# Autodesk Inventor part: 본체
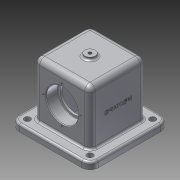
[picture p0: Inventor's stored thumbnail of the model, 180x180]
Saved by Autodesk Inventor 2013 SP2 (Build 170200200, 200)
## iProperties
Created: 2022-07
Part Number: 본체
Material: 알루미늄 6061
Document SubType Name: Modeling
Designer: i
Density: 2.71 g/cm^3
Mass: 1063.76 g
Surface Area: 721.846 cm^2
Volume: 392.531 cm^3
Author: i
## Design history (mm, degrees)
sketch "스케치1"
  geometry: L1 (-41, -40)-(41, -40); L2 (41, -40)-(41, 40); L3 (41, 40)-(-41, 40); L4 (-41, 40)-(-41, -40); L5 (-41, -40)-(41, 40); L6 (41, -40)-(-41, 40); 1 further point
  constraints: 12 end point, 2 midpoint, 2 parallel, 1 horizontal, 1 perpendicular
  dimensions: "d0" = 82 distance of L2.end L3.end; "d2" = 80 distance of L1.end L2.end
extrude "돌출1" new body sketch "스케치1" stored distance "d3" = 82; taper "d4" = 0 deg
sketch "스케치2"
  geometry: L1 (-17, -99)-(99, -99); L2 (99, -99)-(99, 17); L3 (99, 17)-(-17, 17); L4 (-17, 17)-(-17, -99); L5 (-17, -99)-(99, 17); L6 (99, -99)-(-17, 17); 1 further point
  constraints: 12 end point, 2 midpoint, 2 parallel, 1 horizontal, 1 perpendicular
  dimensions: "d5" = 116 distance of L3.end L2.end; "d6" = 116 distance of L2.end L1.end
extrude "돌출2" join sketch "스케치2" distance "d7" = 10; taper "d8" = 0 deg
sketch "스케치3"
  geometry: L1 (41, 40)-(-41, 40) reference; C1 r 23.5 at (0, -2); 1 further point
  constraints: 1 centre point, 1 vertical alignment
  dimensions: "d9" = 47 diameter of C1; "d10" = 42 distance from line of L1 C1.centre
extrude "돌출3" cut sketch "스케치3" distance "d11" = 17; taper "d12" = 0 deg
sketch "스케치4"
  geometry: L1 (11, -62)-(71, -62); L2 (71, -62)-(71, -20); L3 (71, -20)-(11, -20); L4 (11, -20)-(11, -62); L5 (11, -62)-(71, -20); L6 (71, -62)-(11, -20); 1 further point
  constraints: 12 end point, 2 midpoint, 2 parallel, 1 horizontal, 1 perpendicular
  dimensions: "d13" = 60 distance of L3.end L2.end; "d14" = 42 distance of L2.end L1.end
extrude "돌출4" cut sketch "스케치4" distance "d15" = 80; taper "d16" = 0 deg
sketch "스케치5"
  geometry: C1 r 23.5 at (0, 0) reference; C2 r 20 at (0, 0); 1 further point
  constraints: 1 centre point, 1 coincident
  dimensions: "d17" = 40 diameter of C2
extrude "돌출5" cut sketch "스케치5" stored distance "d18" = 80; taper "d19" = 0 deg
fillet "모깎기1" dims "d20" = 0.6
fillet "모깎기2" dims "d21" = 3
fillet "모깎기3" dims "d22" = 3
chamfer "모따기1" distance "d23" = 1; stored, may be unused: second distance "d24" = 2, angle "d25" = 45 deg
fillet "모깎기4" dims "d26" = 8
fillet "모깎기5" dims "d27" = 8
fillet "모깎기6" dims "d28" = 12
fillet "모깎기7" dims "d29" = 3
sketch "스케치6"
  geometry: C1 r 4.5 at (-5, 87); C2 r 4.5 at (87, 87); C3 r 4.5 at (87, -5); C4 r 4.5 at (-5, -5); A1 r 12 centre (-5, 87) between (-5, 99) and (-17, 87) reference; A2 r 12 centre (-5, -5) between (-17, -5) and (-5, -17) reference; A3 r 12 centre (87, -5) between (87, -17) and (99, -5) reference; A4 r 12 centre (87, 87) between (99, 87) and (87, 99) reference; 1 further point
  constraints: 4 centre point, 4 coincident
  dimensions: "d30" = 9 diameter of C1; "d31" = 9 diameter of C2; "d33" = 9 diameter of C3; "d34" = 9 diameter of C4
extrude "돌출6" cut sketch "스케치6" stored distance "d35" = 80; taper "d36" = 0 deg
fillet "모깎기8" dims "d37" = 3
sketch "스케치7"
  geometry: C1 r 7.5 at (33, 33); 1 further point
  constraints: 1 centre point, 1 coincident
  dimensions: "d38" = 15 diameter of C1
extrude "돌출7" join sketch "스케치7" distance "d39" = 4; taper "d40" = 0 deg
sketch "스케치8"
  geometry: C1 r 7.5 at (0, 0) reference; 1 further point
  constraints: 1 coincident
hole "구멍1" sketch "스케치8" at (0, 0) diameter "d41" = 4.917; stored, may be unused: countersink angle "d45" = 90 deg, drill point angle "d47" = 118 deg; dims "d42" = 6, "d43" = 4, "d44" = 2, "d46" = 8
sketch "스케치9"
  geometry: C1 r 24.5 at (0, -2) reference; 2 further points
  constraints: 1 vertical alignment
  dimensions: "d48" = 27 distance of C1.centre point (0, 25)
hole "구멍2" sketch "스케치9" at (0, 25) diameter "d49" = 3.242; stored, may be unused: countersink angle "d53" = 90 deg, drill point angle "d55" = 118 deg; dims "d50" = 8, "d51" = 4, "d52" = 2, "d54" = 10
fillet "모깎기9" dims "d59" = 3
sketch "스케치10"
  geometry: L1 (79, -82)-(-13, -82) reference; 2 further points
  constraints: 1 vertical alignment, 1 other
  dimensions: "d60" = 48 distance from line of L1 point (33, -34)
feature "엠보싱1" sketch "스케치10" dims "d0" = 82, "d2" = 80, "d9" = 47, "d10" = 42, "d61" = 0.5, "d62" = 0
node "솔리드1"
mirror "대칭1"
pattern_circular "원형 패턴1" dims angle "d57" = 360 deg
mirror "대칭2"
